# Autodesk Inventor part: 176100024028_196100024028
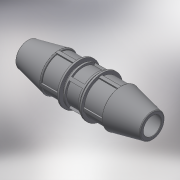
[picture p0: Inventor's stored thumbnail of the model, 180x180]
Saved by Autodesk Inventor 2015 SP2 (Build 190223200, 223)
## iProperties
Created: 2016-12
Part Number: 176100024028_196100024028
Material: Generic
Description: PLASSON UNIVERSAL SLIP REPAIR COUPLER 24-28 SERIES 17
Document SubType Name: Modeling
Designer: KIM
Mass: 305.707 g
Surface Area: 640.661 cm^2
Volume: 305.707 cm^3
Density: 1 g/cm^3
Appearance: Default
Author: KIM
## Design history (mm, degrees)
derived "17610.ipt"
feature "Solid1::17610.ipt"
tag "TaggingFeature1"
body "Solid1"
other parameters: "d5" = 133, "d11" = 33.25, "d12" = 2.66, "d13" = 39.2, "d15" = 28, "d16" = 27.44, "d17" = 52.8, "d20" = 56.1, "d21" = 80 deg, "d22" = 28.57143, "d23" = 0, "d25" = 360 deg, "d31" = 26.6, "d32" = 59.4, "d33" = 80 deg, "d34" = 40 deg, "d35" = 52.8, "d36" = 10.64, "d37" = 0, "d39" = 360 deg, "d41" = 2, "d43" = 360 deg, "d48" = 1.4, "d52" = 0.66, "d55" = 66, "d56" = 60.72, "d_" = 28, "E_" = 66, "l_" = 133
